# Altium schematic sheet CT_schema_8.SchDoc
size 274 x 160 mm
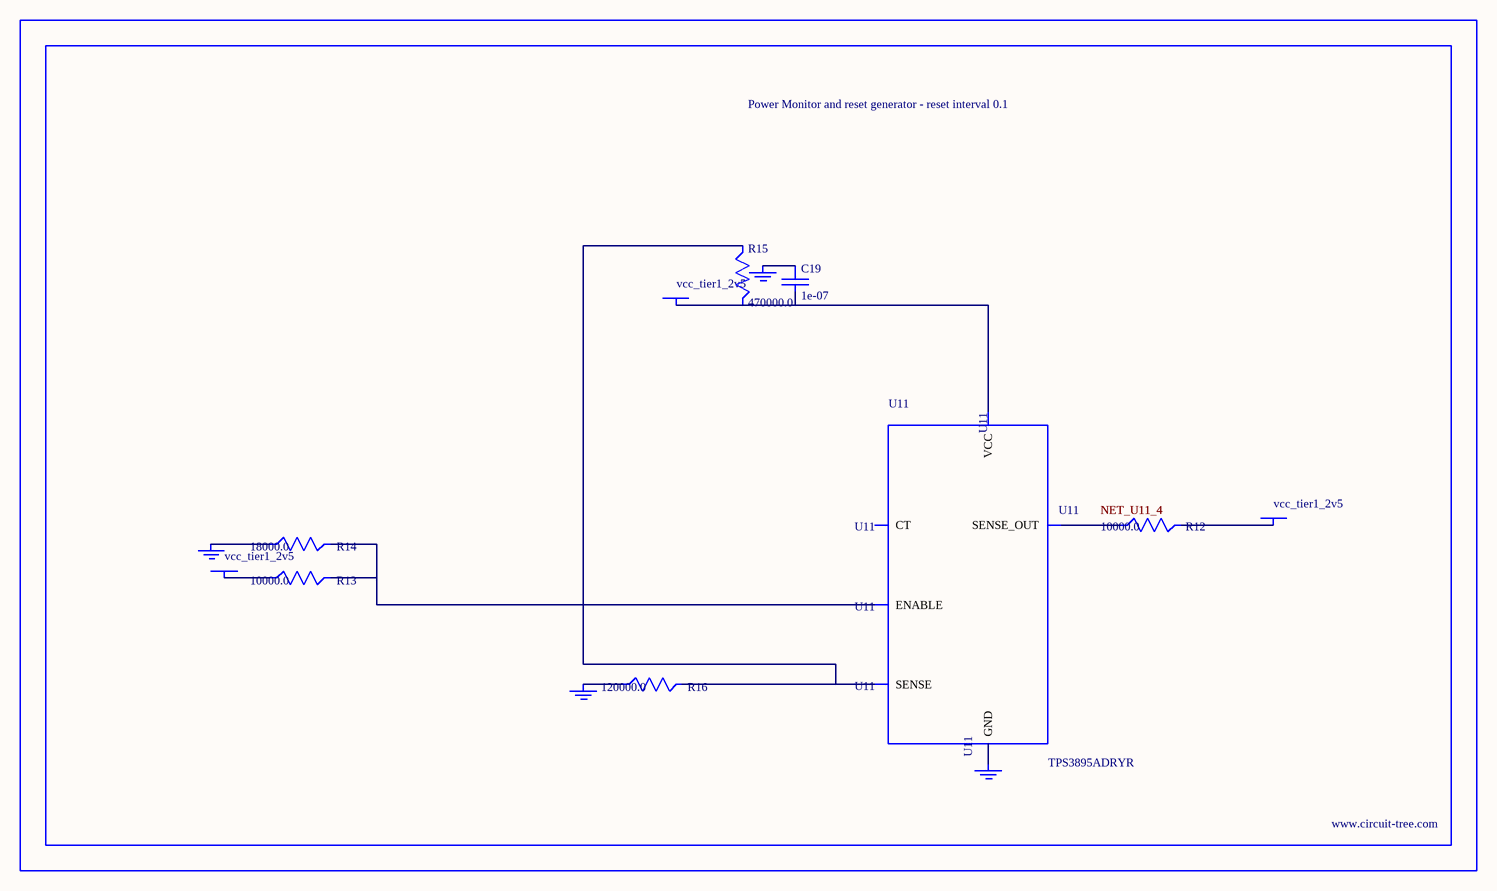
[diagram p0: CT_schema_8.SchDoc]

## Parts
BORDER7  (no value)
C19  1e-07  [C0402]
GND_INSTANCE_7_0  (no value)
GND_INSTANCE_7_1  (no value)
GND_INSTANCE_7_2  (no value)
GND_INSTANCE_7_3  (no value)
POWER_INSTANCE_7_0  vcc_tier1_2v5
POWER_INSTANCE_7_1  vcc_tier1_2v5
POWER_INSTANCE_7_2  vcc_tier1_2v5
R12  10000.0  [R0603]
R13  10000.0  [R0603]
R14  18000.0  [R0603]
R15  470000.0  [R0603]
R16  120000.0  [R0603]
U11  TPS3895ADRYR  [SON-6]

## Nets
NetC19_1: C19.1 GND_INSTANCE_7_2.0(GND)
NetC19_2: C19.2 POWER_INSTANCE_7_2.0(PWR) R15.2 U11.6(VCC)
NetGND_INSTANCE_7_0_0: GND_INSTANCE_7_0.0(GND) R14.1
NetGND_INSTANCE_7_1_0: GND_INSTANCE_7_1.0(GND) R16.1
NetGND_INSTANCE_7_3_0: GND_INSTANCE_7_3.0(GND) U11.2(GND)
NetPOWER_INSTANCE_7_0_0: POWER_INSTANCE_7_0.0(PWR) R13.1
NetPOWER_INSTANCE_7_1_0: POWER_INSTANCE_7_1.0(PWR) R12.2
NetR12_1: R12.1 U11.4(SENSE_OUT)
NetR13_2: R13.2 R14.2 U11.1(ENABLE)
NetR15_1: R15.1 R16.2 U11.3(SENSE)

Not connected (* = marked no-connect by the designer): U11 5(CT)

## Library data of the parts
BORDER7 = BORDER_PAGE7
C19 = C0402C104K3RACTU
GND_INSTANCE_7_0-GND_INSTANCE_7_3 = GND
POWER_INSTANCE_7_0-POWER_INSTANCE_7_2 = PWR
R12 R13 = RC0603JR-0710KL
R14 = RC0603JR-0718KL
R15 = RC0603JR-07470KL
R16 = RC0603JR-07120KL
